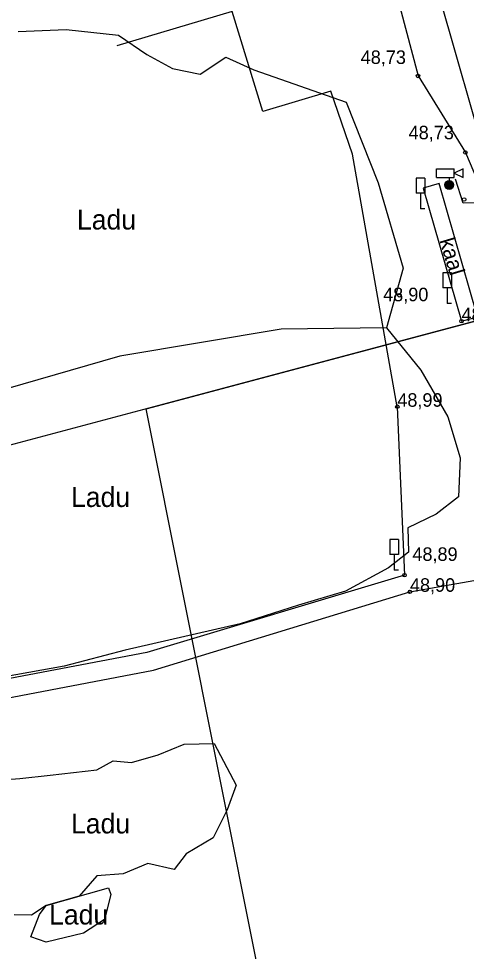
# Model space of a CAD drawing. Extents: x 700746 to 706058, y 6570320 to 6580460.
# Drawn here: x 702817.1 to 702898.3, y 6576775.9 to 6576945 of the extents above; entities that cross this region are included whole.
import ezdxf

# ---------------------------------------------------------------- set-up
doc = ezdxf.new("R2010")
doc.units = 0
for name, color, linetype in [('HALJASTUS', 7, 'Continuous'), ('kataster', 7, 'Continuous'), ('KORGUS-EH2000', 7, 'Continuous'), ('KPKAABEL', 7, 'Continuous'), ('LIIKLUS', 7, 'Continuous'), ('Plokid', 7, 'Continuous'), ('POST', 7, 'Continuous'), ('RAJATIS', 7, 'Continuous'), ('RELJEEF', 7, 'Continuous'), ('TEE', 7, 'Continuous'), ('VWX2_MV_PLOKK', 7, 'Continuous')]:
    doc.layers.add(name, color=color, linetype=linetype)

msp = doc.modelspace()

# ---------------------------------------------------------------- linework, layer by layer
at = {"layer": 'kataster'}
msp.add_lwpolyline([(702723.93, 6577008.77), (702873.9, 6577049.58), (702915.96, 6576894.45), (702764.55, 6576854.07)], close=True, dxfattribs=at)
at = {"layer": 'KORGUS-EH2000'}
for centre in [(702889.52, 6576934.59), (702898.1, 6576920.72), (702897.89, 6576912.19), (702886.13, 6576894.83), (702897.4, 6576890.14), (702885.77, 6576874.63), (702887.07, 6576844.1), (702888.06, 6576841.09)]:
    msp.add_circle(centre, 0.32, dxfattribs=at)
at = {"layer": 'KPKAABEL'}
msp.add_line((702886.21, 6576974.21), (702904.71, 6576909.22), dxfattribs=at)
at = {"layer": 'LIIKLUS'}
for p, q in [((702889.16, 6576916.08), (702889.16, 6576913.36)), ((702890.76, 6576916.08), (702889.16, 6576916.08)), ((702890.76, 6576916.08), (702890.76, 6576913.36)), ((702890.76, 6576913.36), (702889.16, 6576913.36)), ((702889.96, 6576913.36), (702889.96, 6576910.48)), ((702890.76, 6576910.48), (702889.96, 6576910.48)), ((702893.99, 6576898.93), (702893.99, 6576896.21)), ((702895.59, 6576898.93), (702893.99, 6576898.93)), ((702895.59, 6576898.93), (702895.59, 6576896.21)), ((702895.59, 6576896.21), (702893.99, 6576896.21)), ((702894.79, 6576896.21), (702894.79, 6576893.33)), ((702895.59, 6576893.33), (702894.79, 6576893.33)), ((702884.4, 6576850.58), (702884.4, 6576847.86)), ((702886, 6576850.58), (702884.4, 6576850.58)), ((702886, 6576850.58), (702886, 6576847.86)), ((702886, 6576847.86), (702884.4, 6576847.86)), ((702885.2, 6576847.86), (702885.2, 6576844.98)), ((702886, 6576844.98), (702885.2, 6576844.98))]:
    msp.add_line(p, q, dxfattribs=at)
at = {"layer": 'Plokid'}
msp.add_lwpolyline([(702900.72, 6576571.25), (702840.26, 6576874.26), (702936.9, 6576900.04)], dxfattribs=at)
at = {"layer": 'POST'}
for p, q in [((702892.86, 6576917.78), (702896.06, 6576917.78)), ((702892.86, 6576916.18), (702892.86, 6576917.78)), ((702896.06, 6576916.18), (702896.06, 6576917.78)), ((702897.71, 6576917.78), (702896.06, 6576916.98)), ((702897.71, 6576916.18), (702897.71, 6576917.78)), ((702892.86, 6576916.18), (702896.06, 6576916.18)), ((702895.18, 6576916.18), (702895.18, 6576914.84)), ((702896.06, 6576916.98), (702897.71, 6576916.18))]:
    msp.add_line(p, q, dxfattribs=at)
for radius in [0.8, 0.72, 0.64, 0.56, 0.48, 0.4, 0.32, 0.24, 0.16, 0.08]:
    msp.add_circle((702895.18, 6576914.84), radius, dxfattribs=at)
at = {"layer": 'RAJATIS'}
msp.add_lwpolyline([(702890.48, 6576914.26), (702897.4, 6576890.14), (702900.31, 6576890.96), (702893.38, 6576915.1)], close=True, dxfattribs=at)
at = {"layer": 'RELJEEF'}
for points in [[(702817.01, 6576942.68), (702825.77, 6576943.03), (702835.21, 6576941.98), (702840.35, 6576938.51), (702845, 6576935.92), (702850.02, 6576934.92), (702854.71, 6576937.98), (702859.76, 6576935.73), (702876.52, 6576929.83), (702882.28, 6576915.23), (702886.8, 6576899.78), (702883.8, 6576888.91), (702890.01, 6576881.25), (702894.93, 6576872.79), (702897.17, 6576865.35), (702896.88, 6576858.29), (702892.79, 6576855.14), (702887.68, 6576852.68), (702887.82, 6576848.25), (702884.18, 6576845.45), (702876.4, 6576841.21), (702867.86, 6576838.67), (702857.29, 6576835.3), (702836.44, 6576830.5), (702825.36, 6576827.62), (702810.14, 6576824.89)], [(702883.8, 6576888.91), (702864.69, 6576888.69), (702835.47, 6576883.79), (702814.72, 6576877.82), (702796.31, 6576870.97), (702784.09, 6576874.99)], [(702812.42, 6576806.87), (702817.32, 6576807.21), (702822.82, 6576807.84), (702831.28, 6576808.79), (702834.23, 6576810.44), (702837.6, 6576810.15), (702842.4, 6576811.53), (702847.15, 6576813.44), (702852.55, 6576813.59), (702856.56, 6576806.02), (702854.95, 6576801.54), (702852.41, 6576796.47), (702847.51, 6576793.61), (702845.29, 6576790.76), (702840.57, 6576791.81), (702836.1, 6576789.97), (702831.27, 6576789.58), (702828.1, 6576785.93), (702822.09, 6576784.21), (702819.44, 6576782.49), (702816.29, 6576782.51)]]:
    msp.add_lwpolyline(points, dxfattribs=at)
msp.add_lwpolyline([(702820.88, 6576782.6), (702822.09, 6576784.21), (702833.42, 6576787.41), (702833.86, 6576786.19), (702832.66, 6576781.69), (702828.88, 6576779.2), (702822.11, 6576777.6), (702819.31, 6576778.55)], close=True, dxfattribs=at)
at = {"layer": 'TEE'}
for points in [[(702804.2, 6577087.34), (702821.19, 6577083.63), (702833.12, 6577079.74), (702843.06, 6577073.68), (702853, 6577063.74), (702859.05, 6577053.07), (702864.74, 6577031.1), (702873.85, 6576998.92), (702879.79, 6576971.27), (702889.52, 6576934.59)], [(702885.77, 6576874.63), (702877.67, 6576920.43), (702873.73, 6576931.82), (702861.4, 6576928.18), (702855.86, 6576946.28), (702834.9, 6576940.05)], [(702889.52, 6576934.59), (702898.1, 6576920.72), (702902.01, 6576911.57), (702897.69, 6576911.55), (702896.31, 6576915.89)], [(702885.77, 6576874.63), (702887.07, 6576844.1), (702840.39, 6576830.08), (702797.63, 6576821.97)], [(702798.82, 6576818.74), (702841.58, 6576826.85), (702888.06, 6576841.09), (702901.35, 6576843.43), (702906.32, 6576839.42), (702921.23, 6576784.91)]]:
    msp.add_lwpolyline(points, dxfattribs=at)
at = {"layer": 'VWX2_MV_PLOKK'}
msp.add_lwpolyline([(702840.26, 6576874.26), (702915.96, 6576894.45), (703039.76, 6576927.49), (703072.13, 6576856.26), (703101.31, 6576579.97), (703076.01, 6576303.02), (703067.36, 6576229.67), (702842.72, 6576158.42), (702853.4, 6576267.5), (702860.12, 6576517.75), (702877.29, 6576548.25), (702900.72, 6576571.25)], close=True, dxfattribs=at)
msp.add_lwpolyline([(702840.26, 6576874.26), (702915.96, 6576894.45), (703039.76, 6576927.49), (703072.13, 6576856.26), (703101.31, 6576579.97), (703076.01, 6576303.02), (703067.36, 6576229.67), (702842.72, 6576158.42), (702853.4, 6576267.5), (702860.12, 6576517.75), (702877.29, 6576548.25), (702900.72, 6576571.25)], close=True, dxfattribs=at)

# ---------------------------------------------------------------- texts
at = {"layer": 'HALJASTUS'}
for p in [(702827.7, 6576906.76), (702826.62, 6576856.46), (702826.62, 6576797.28), (702822.65, 6576780.77)]:
    msp.add_text('Ladu', height=3.6, dxfattribs=at).set_placement(p)
at = {"layer": 'KORGUS-EH2000'}
for s, p in [('48,73 ', (702879.13, 6576936.77)), ('48,73 ', (702887.82, 6576923.12)), ('48,90 ', (702883.2, 6576893.76)), ('48,99 ', (702897.4, 6576890.14)), ('48,99 ', (702885.77, 6576874.63)), ('48,89 ', (702888.5, 6576846.69)), ('48,90 ', (702888.06, 6576841.09))]:
    msp.add_text(s, height=2.45, dxfattribs=at).set_placement(p)
at = {"layer": 'RAJATIS'}
msp.add_text('kaal', height=2.8, rotation=286.8051, dxfattribs=at).set_placement((702893.38, 6576904.79))

doc.saveas('drawing.dxf')
